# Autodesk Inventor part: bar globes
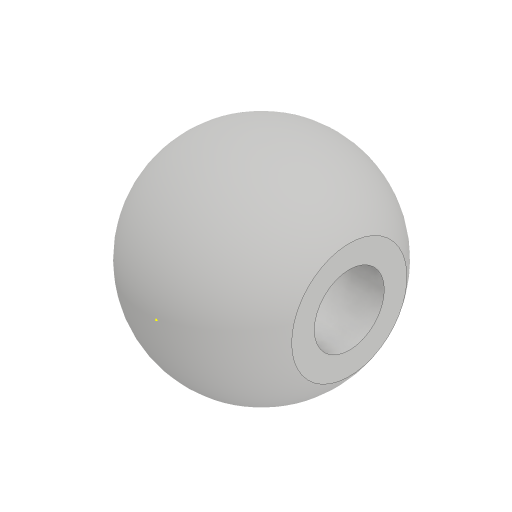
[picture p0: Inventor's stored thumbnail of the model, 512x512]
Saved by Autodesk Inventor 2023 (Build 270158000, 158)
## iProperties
Created: 2016-03
Part Number: bar globes
Material: Generic
Document SubType Name: Modeling
Designer: Sandeep
Density: 1 g/cm^3
Appearance: Default
Mass: 0.753654 g
Surface Area: 5.66286 cm^2
Volume: 0.753654 cm^3
Author: Sandeep
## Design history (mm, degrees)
sketch "Sketch1"
  geometry: L1 (0, 12)-(0, 0); A1 r 6 centre (0, 6) between (0, 12) and (0, 0)
  constraints: 2 end point, 2 point on circle, 1 centre point, 1 midpoint, 1 vertical
revolve "Revolution1" sketch "Sketch1" stored, may be unused: angle "d1" = 90 deg
sketch "Sketch2"
  geometry: 1 further point
sketch "Sketch3"
  geometry: 1 further point
sketch "Sketch4"
  geometry: 1 further point
sketch "Sketch5"
  geometry: L1 (5.014, 9.295)-(5.014, 2.705); A1 r 6 centre (0, 6) between (0, 0) and (5.014, 9.295) reference; A2 r 6 centre (0, 6) between (0, 0) and (5.014, 2.705) reference; 2 further points
  constraints: 2 end point, 2 point on circle, 1 vertical, 1 vertical alignment
extrude "Extrusion1" cut sketch "Sketch5" stored distance "d2" = 10; taper "d3" = 0 deg
sketch "Sketch6"
  geometry: L1 (5.65, 4.164)-(5.65, -4.091); A1 r 6 centre (0, 0) between (-5.014, -3.295) and (-5.014, 3.295) reference; 1 further point
  constraints: 2 end point, 1 vertical
extrude "Extrusion2" cut sketch "Sketch6" distance "d5" = 15.75; taper "d6" = 0 deg
sketch "Sketch7"
  geometry: L1 (-5.65, 3.981)-(-5.65, 8.019) reference; L2 (-5.65, 6)-(5.014, 6); L3 (-4.986, 8)-(5.014, 8); L4 (5.014, 8)-(5.014, 6); L5 (5.014, 9.295)-(5.014, 2.705) reference; L6 (-5.65, 7.336)-(-5.65, 6); L7 (-4.986, 8)-(-5.65, 7.336); 3 further points
  constraints: 10 end point, 2 collinear, 2 horizontal, 2 midpoint, 2 point on line
  dimensions: "d16" = 4 diameter of L3 L2; "d17" = 10 distance of L3.end L3.start; "d19" = 45 deg angle of L7 L3
revolve "Revolution2" sketch "Sketch7" stored, may be unused: angle "d18" = 90 deg
body "Solid1"
other parameters: "d4" = 15.75
